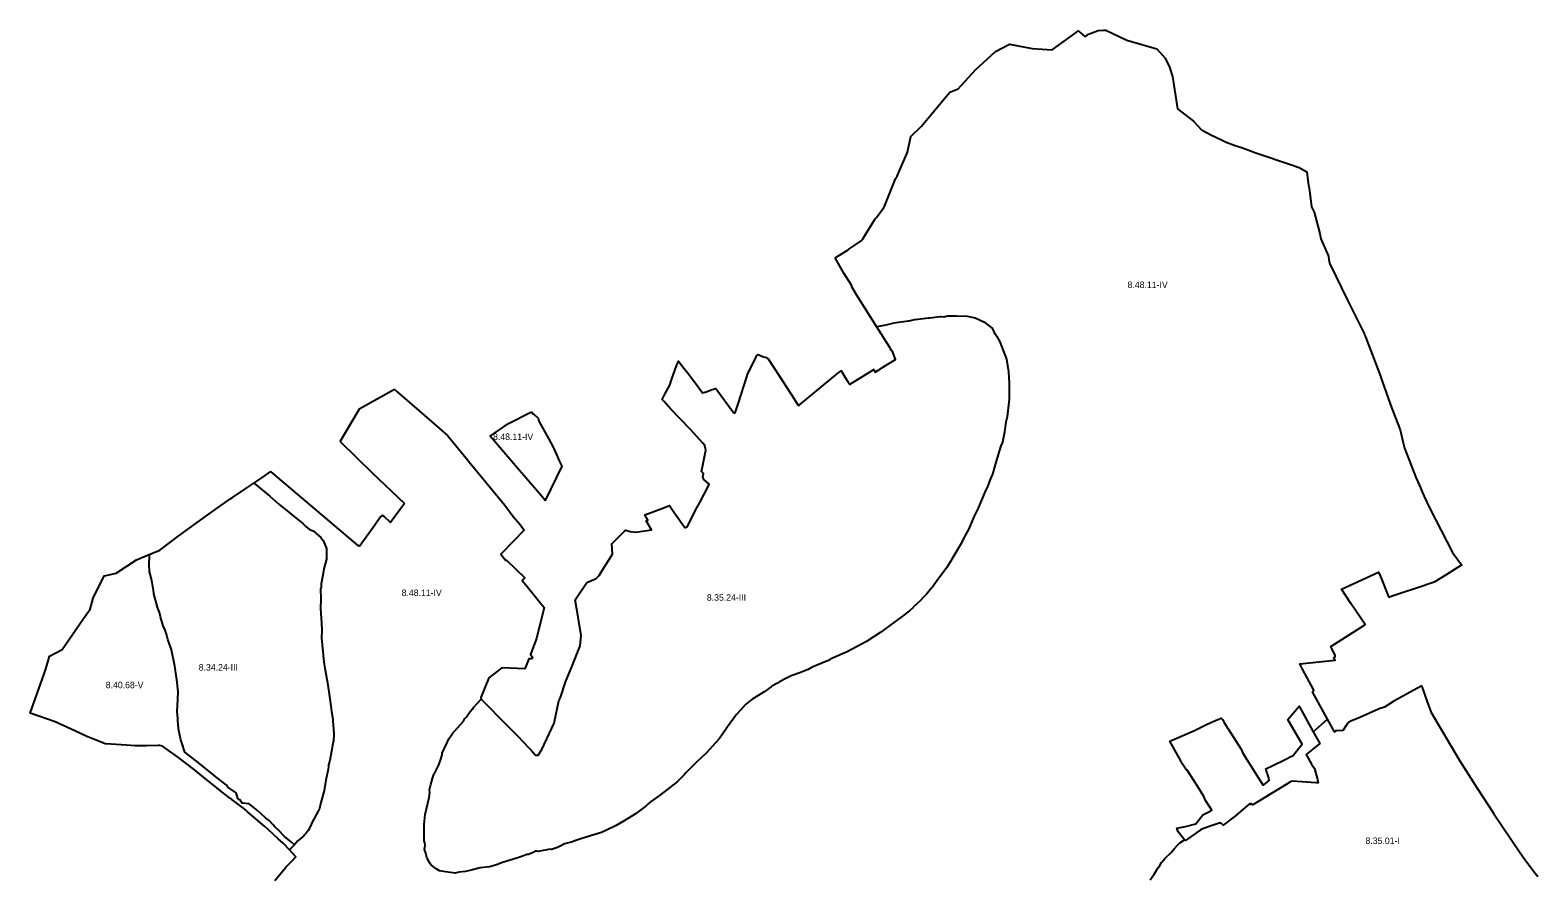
# Model space of a CAD drawing. Extents: x -444937 to -440470, y -1149084 to -1129741.
# Drawn here: x -443281 to -440963, y -1131040 to -1129741 of the extents above; entities that cross this region are included whole.
import ezdxf

# ---------------------------------------------------------------- set-up
doc = ezdxf.new("R2010")
doc.units = 0
doc.layers.add('Vrstva 28', color=7, linetype='Continuous')

msp = doc.modelspace()

# ---------------------------------------------------------------- linework, layer by layer
at = {"layer": 'Vrstva 28'}
for points in [[(-442043.23, -1130091.53), (-442040.49, -1130089.83), (-442039.92, -1130089.47), (-442039.17, -1130089.01), (-442023.03, -1130078.94), (-442021.83, -1130078.19), (-442012.81, -1130071.6), (-442003.19, -1130064.95), (-442000.52, -1130061.9), (-441981.34, -1130031.18), (-441979.75, -1130029.1), (-441968.28, -1130014.12), (-441967.99, -1130013.39), (-441951.57, -1129972.43), (-441949.67, -1129968.93), (-441947.95, -1129965.69), (-441931.73, -1129928.7), (-441926.71, -1129904.58), (-441910.67, -1129889.51), (-441869.52, -1129839.61), (-441866.98, -1129836.53), (-441853.91, -1129831.34), (-441827.5, -1129802.31), (-441796.73, -1129773.78), (-441775.18, -1129762.53), (-441740.41, -1129769.48), (-441709.58, -1129771.58), (-441668.73, -1129742.39), (-441666.17, -1129744.67), (-441659.09, -1129750.95), (-441655.75, -1129748.76), (-441653.67, -1129747.4), (-441638.81, -1129741.44), (-441630.48, -1129741.2), (-441627.01, -1129741.1)], [(-441627.01, -1129741.1), (-441594.36, -1129756.43), (-441548.54, -1129769.98), (-441535.75, -1129784.43), (-441528.76, -1129798.16), (-441524.48, -1129812.45), (-441516.67, -1129862.35), (-441492, -1129881.15), (-441479.58, -1129894.54), (-441478.61, -1129895.06), (-441464.46, -1129902.63), (-441458.68, -1129905.42), (-441448.22, -1129910.45), (-441441.62, -1129913.46), (-441428.07, -1129918.35), (-441415.24, -1129922.84), (-441397.66, -1129929.24), (-441396.28, -1129929.7), (-441343.12, -1129947.52), (-441329.41, -1129952.5), (-441318.04, -1129958.98), (-441316.2, -1129972.39), (-441315.02, -1129979.71), (-441314.71, -1129981.72), (-441313.77, -1129987.9), (-441310.82, -1130012.82), (-441306.53, -1130021.22), (-441297.94, -1130054.03), (-441296.52, -1130061.93), (-441284.64, -1130088.57), (-441284.44, -1130089.91), (-441283.82, -1130094.05), (-441283.09, -1130098.88), (-441282.96, -1130099.77), (-441282.57, -1130100.57), (-441255.11, -1130156.43), (-441229.36, -1130208.81), (-441228.53, -1130210.99), (-441227.78, -1130212.95), (-441204.67, -1130273.29), (-441204.43, -1130273.92), (-441189.48, -1130315.91), (-441186.17, -1130325.54), (-441174.46, -1130355.71), (-441170.23, -1130373.91), (-441167.88, -1130383.99), (-441160.47, -1130402.47), (-441149.43, -1130430.01), (-441144.79, -1130441.59), (-441137.17, -1130458.28), (-441128.64, -1130476.95), (-441094.04, -1130544.82), (-441079.55, -1130563.82), (-441079.42, -1130564), (-441082.38, -1130565.83), (-441090.64, -1130570.93), (-441103.48, -1130578.86), (-441122.26, -1130590.45), (-441129.52, -1130592.88), (-441139.81, -1130596.32), (-441181.79, -1130610.37), (-441185.15, -1130611.45), (-441189.02, -1130612.7), (-441191.79, -1130613.59)], [(-441979.49, -1130196.91), (-442010.04, -1130148.31), (-442017.48, -1130135.77), (-442018.12, -1130133.43), (-442029.81, -1130114.93), (-442043.23, -1130091.53)], [(-441839.96, -1130181.05), (-441828.05, -1130183.39), (-441814.24, -1130189.98), (-441801.69, -1130199.33), (-441798.72, -1130206.35), (-441794.04, -1130212.73), (-441791.77, -1130216.92), (-441789.79, -1130220.59), (-441779.8, -1130246.96), (-441776.61, -1130266.51), (-441775.33, -1130283.95), (-441775.76, -1130308.61), (-441778.52, -1130335.82), (-441780.65, -1130344.32), (-441781.54, -1130351.48), (-441782.56, -1130359.63), (-441785.75, -1130374.94), (-441786.02, -1130375.47), (-441787.87, -1130379.19), (-441791.06, -1130388.54), (-441797.59, -1130411.29), (-441801.27, -1130424.26), (-441802.2, -1130426.37), (-441805.31, -1130433.4), (-441808.71, -1130443.82), (-441811.7, -1130449.35), (-441812.96, -1130451.68), (-441819.53, -1130467.43), (-441822.1, -1130473.58), (-441822.51, -1130474.41), (-441822.72, -1130474.84), (-441822.89, -1130475.18), (-441829.54, -1130488.68), (-441837.83, -1130509.3), (-441844.64, -1130521.2), (-441849.1, -1130530.56), (-441863.63, -1130555.01), (-441865.65, -1130558.4), (-441871.17, -1130567.7), (-441871.21, -1130567.76), (-441886.11, -1130587.63), (-441894.17, -1130598.38), (-441895.51, -1130599.99), (-441902.25, -1130608.15), (-441907.57, -1130613.81), (-441911.95, -1130618.46), (-441912.45, -1130619), (-441923.12, -1130628.83), (-441923.85, -1130629.5), (-441928.82, -1130634.09), (-441941.58, -1130644.3), (-441968.75, -1130664.12), (-441969.87, -1130664.94), (-441971.34, -1130666.01), (-441973.05, -1130667.26), (-441995.16, -1130681.29), (-442024.72, -1130697.21), (-442028.32, -1130699.15), (-442043.44, -1130705.67), (-442047.03, -1130707.22), (-442051.19, -1130709.42), (-442053.38, -1130710.57), (-442054.68, -1130711.26), (-442078.49, -1130721.04), (-442084.44, -1130724.44), (-442098.9, -1130730.4), (-442110.81, -1130734.22), (-442114.65, -1130736.22), (-442117.79, -1130737.86), (-442128.69, -1130743.52), (-442131.9, -1130745.32), (-442140.57, -1130750.17), (-442141.69, -1130751.02), (-442150.61, -1130757.84), (-442152.26, -1130759.1), (-442163.02, -1130765.72), (-442169.47, -1130769.7), (-442173.31, -1130772.07), (-442180.96, -1130778.23), (-442188.89, -1130787.12), (-442194.99, -1130793.96), (-442196.33, -1130795.82), (-442208.55, -1130812.83), (-442209.42, -1130814.04), (-442211.7, -1130817.22), (-442221.57, -1130830.95), (-442241.34, -1130853.06), (-442256.22, -1130867.09), (-442256.28, -1130867.15), (-442273.04, -1130884.03), (-442274.98, -1130885.99), (-442286.2, -1130897.28), (-442313.2, -1130918.54), (-442327.23, -1130928.32), (-442331.26, -1130931.85), (-442333.83, -1130934.1), (-442335.73, -1130935.76), (-442350.19, -1130946.39), (-442367.66, -1130957.13)], [(-441979.49, -1130196.91), (-441978.44, -1130196.74), (-441964.54, -1130194.44), (-441954.19, -1130191.86), (-441949.23, -1130190.62), (-441930.66, -1130188.25), (-441929.25, -1130188.07), (-441921.04, -1130186.39), (-441919.9, -1130186.15), (-441899.77, -1130183.8), (-441897.29, -1130183.51), (-441881.64, -1130181.67), (-441879.93, -1130181.47), (-441876.1, -1130181.9), (-441870.15, -1130180.62), (-441856.54, -1130180.41), (-441839.96, -1130181.05)], [(-442020.82, -1130286.01), (-441987.93, -1130265.66), (-441983.86, -1130263.14), (-441983.7, -1130263.41), (-441981.52, -1130267.12), (-441973.17, -1130261.95), (-441971.23, -1130260.75), (-441950.1, -1130247.67), (-441954.62, -1130236.67), (-441956.47, -1130233.71), (-441959.25, -1130229.27), (-441979.49, -1130196.91)], [(-442433.7, -1130672.39), (-442438.82, -1130641.1), (-442442.7, -1130617.43), (-442425.08, -1130590.72), (-442410.35, -1130584.67), (-442405.99, -1130579.98), (-442401.18, -1130572.38), (-442385.25, -1130547.17), (-442386.53, -1130531.38), (-442372.85, -1130517.54), (-442366.77, -1130511), (-442365.07, -1130510.15), (-442358.27, -1130512.27), (-442349.76, -1130513.55), (-442325.44, -1130509.6), (-442333.77, -1130495.69), (-442331.01, -1130494.8), (-442332.54, -1130492.29), (-442334.31, -1130489.4), (-442336.01, -1130486.62), (-442325.81, -1130482.86), (-442309.69, -1130476.92), (-442300.54, -1130473.55), (-442297.58, -1130472.46), (-442295.76, -1130475.28), (-442292.89, -1130479.91), (-442290.88, -1130483.15), (-442286.68, -1130488.9), (-442284.05, -1130492.52), (-442280.75, -1130497.03), (-442274.29, -1130505.9), (-442272.8, -1130506.32), (-442272.06, -1130505.82), (-442270.89, -1130505.05), (-442255.78, -1130476.07), (-442251.43, -1130467.72), (-442239.12, -1130444.1), (-442236.7, -1130439.47), (-442245.12, -1130432.2), (-442246.63, -1130428.44), (-442245.69, -1130422.94), (-442248.57, -1130420.01), (-442247.13, -1130412.78), (-442242.08, -1130387.35), (-442243.5, -1130380.36), (-442243.59, -1130379.9), (-442247.33, -1130375.82), (-442264.97, -1130356.15), (-442266.43, -1130354.53), (-442295.76, -1130323.91), (-442299.37, -1130319.91), (-442306.2, -1130312.32), (-442309.16, -1130309.03), (-442308.79, -1130308.36), (-442304.93, -1130301.19), (-442297.46, -1130287.35), (-442294.57, -1130278.93), (-442286.62, -1130255.88), (-442284.61, -1130251.59), (-442284.04, -1130250.36), (-442283.73, -1130250.75), (-442277.61, -1130258.54), (-442270.68, -1130267.36), (-442259.58, -1130282.17), (-442247.08, -1130298.83), (-442241.34, -1130297.55), (-442231.99, -1130293.94), (-442228.39, -1130292.65), (-442226.78, -1130292.07), (-442199.46, -1130329.02), (-442197.55, -1130330.08), (-442197.27, -1130329.94), (-442196.69, -1130329.65), (-442194.14, -1130322.21), (-442191.6, -1130314.25), (-442178.82, -1130274.26), (-442177.77, -1130270.98), (-442164.81, -1130243.63), (-442164.17, -1130242.28), (-442162.25, -1130239.94), (-442160.68, -1130240.58), (-442153.33, -1130243.55), (-442149.29, -1130244.4), (-442147.1, -1130245.92), (-442146.52, -1130246.32), (-442146.19, -1130246.82), (-442128.87, -1130273.22), (-442105.89, -1130308.24), (-442100.39, -1130317.32), (-442099.33, -1130318.39), (-442098.48, -1130318.17), (-442039.37, -1130269.07), (-442034.07, -1130265.25), (-442033.59, -1130266.01), (-442033.18, -1130265.67), (-442027.66, -1130275.3), (-442022.86, -1130282.82), (-442021.73, -1130284.58), (-442020.82, -1130286.01)], [(-442804.09, -1130373.76), (-442776.45, -1130327.08), (-442774.04, -1130323.01), (-442720.69, -1130293.35)], [(-442720.69, -1130293.35), (-442716.51, -1130297.67), (-442682.91, -1130326.42), (-442651.72, -1130353.78), (-442638.9, -1130365.03), (-442607.72, -1130402.76), (-442606.77, -1130403.91), (-442550.89, -1130471.96), (-442538.14, -1130488.97), (-442527.51, -1130501.72), (-442525.44, -1130504.67), (-442521.55, -1130510.23), (-442556.21, -1130546.37), (-442557.22, -1130547.38), (-442551.46, -1130554.43), (-442549.35, -1130557), (-442548.67, -1130556.55), (-442520.3, -1130583.3), (-442524.35, -1130587.57), (-442518.74, -1130594.43), (-442495.48, -1130622.9), (-442490.57, -1130628.93), (-442502.12, -1130676.66), (-442503.17, -1130679.42), (-442511.68, -1130701.43), (-442507.95, -1130706.02), (-442509.44, -1130708.14), (-442514.35, -1130708.33), (-442520.25, -1130723.59), (-442555.52, -1130721.77), (-442575.4, -1130737.4), (-442587.88, -1130767.45), (-442587.51, -1130770.05)], [(-442500, -1130338.12), (-442498.79, -1130342.62), (-442483.88, -1130369.46), (-442476.9, -1130382.59), (-442470.16, -1130397.39), (-442467.28, -1130403.83), (-442463.43, -1130411.9), (-442488.8, -1130464.73), (-442495.89, -1130456.48), (-442518.83, -1130429.78), (-442531.49, -1130414.9), (-442573.49, -1130365.51), (-442545.58, -1130346.1), (-442510.06, -1130328.22)], [(-442510.06, -1130328.22), (-442507.97, -1130331.59), (-442507.17, -1130331.16), (-442500, -1130338.12)], [(-442804.09, -1130373.76), (-442754.81, -1130421.97), (-442705.43, -1130469.26)], [(-442936.98, -1130437.83), (-442924.6, -1130429.5), (-442910.63, -1130420.09)], [(-442705.43, -1130469.26), (-442726.82, -1130498.57), (-442736.69, -1130489.18), (-442739.03, -1130487.91), (-442740.3, -1130488.12), (-442742, -1130489.82), (-442750.96, -1130502.49), (-442773.25, -1130534.04), (-442774.95, -1130534.67), (-442776.02, -1130534.25), (-442906.77, -1130423.37), (-442910.63, -1130420.09)], [(-443097.02, -1130547.24), (-443095.23, -1130546.49), (-443081.71, -1130540.83), (-443053.63, -1130519.95), (-443027.65, -1130501.18), (-442998.28, -1130479.96), (-442974.07, -1130462.8), (-442969.91, -1130460), (-442948.01, -1130445.26), (-442936.98, -1130437.83)], [(-442936.98, -1130437.83), (-442936.7, -1130438.06), (-442935.36, -1130439.15), (-442912.28, -1130457.93), (-442898.68, -1130470.05), (-442861.9, -1130499.81), (-442856.8, -1130504.7), (-442851.48, -1130508.95), (-442845.72, -1130511.39)], [(-442845.72, -1130511.39), (-442833.97, -1130521.68), (-442830.38, -1130526.26), (-442825.42, -1130538.49), (-442825.14, -1130555.02), (-442829.38, -1130569.75), (-442830.34, -1130576.35), (-442830.38, -1130576.65), (-442831.42, -1130581.78), (-442833.63, -1130592.71), (-442833.63, -1130598.66), (-442834.26, -1130600.36), (-442833.84, -1130616.09), (-442834.48, -1130630.55), (-442833.49, -1130646.29), (-442833.08, -1130652.93), (-442832.35, -1130664.56), (-442832.78, -1130675.62), (-442829.38, -1130713.03), (-442827.66, -1130722.55), (-442823.64, -1130744.92), (-442820.68, -1130765.84), (-442818.54, -1130780.96), (-442817.39, -1130789.1), (-442815.71, -1130801.02), (-442815.34, -1130803.59), (-442814.31, -1130816.56), (-442814.28, -1130817.01), (-442813.86, -1130822.3), (-442814.05, -1130825.13), (-442814.71, -1130834.63), (-442814.94, -1130835.95), (-442820.02, -1130864.39), (-442821.94, -1130871.19), (-442822.32, -1130874.03), (-442823.21, -1130880.55), (-442826.4, -1130895), (-442827.17, -1130900.76), (-442828.1, -1130907.76), (-442828.89, -1130910.76), (-442834.34, -1130931.41), (-442836.18, -1130938.37), (-442838.31, -1130942.53), (-442847.59, -1130960.64), (-442850.07, -1130965.48), (-442853.5, -1130972.17), (-442853.61, -1130972.38), (-442856.76, -1130976.26), (-442859.03, -1130979.06), (-442859.99, -1130980.25), (-442863.39, -1130983.17), (-442869.13, -1130988.11), (-442872.84, -1130992.45), (-442874.33, -1130994.19)], [(-442882.23, -1131001.82), (-442891.39, -1130992.04), (-442895.35, -1130988.44), (-442899.33, -1130984.82), (-442906.63, -1130978.19), (-442915.59, -1130970.05), (-442919.98, -1130966.06), (-442940.07, -1130948.87), (-442946.49, -1130943.37), (-442949.68, -1130940.64), (-442952.16, -1130938.52), (-442960.65, -1130932.13), (-442970.89, -1130924.41), (-442971.95, -1130923.61), (-442972.2, -1130923.41), (-442974.22, -1130921.83), (-442988, -1130911.01), (-443002.15, -1130899.89), (-443003.41, -1130898.87), (-443009.46, -1130894.01), (-443030.66, -1130876.94), (-443054.28, -1130859.03), (-443054.57, -1130858.81), (-443070.13, -1130847.71), (-443077.41, -1130842.52), (-443081.59, -1130841.29), (-443084.12, -1130841.36), (-443102.37, -1130841.84), (-443109.42, -1130842.03), (-443110.44, -1130841.97), (-443118.52, -1130841.76), (-443119.22, -1130841.72), (-443133.41, -1130840.86), (-443156.14, -1130839.47), (-443165.45, -1130838.96), (-443176.89, -1130834.39), (-443192.31, -1130828.23), (-443192.7, -1130828.08), (-443204.51, -1130822.59), (-443230.29, -1130810.62), (-443242.27, -1130805.06), (-443280.95, -1130791.54), (-443259.33, -1130731.05), (-443257.22, -1130725.15), (-443253.77, -1130713.08), (-443251.22, -1130704.16), (-443231.83, -1130693.59), (-443199.74, -1130647.63), (-443198.69, -1130646.13), (-443188.44, -1130631.49), (-443184.16, -1130614.88), (-443167.28, -1130580.57), (-443161.99, -1130579.3), (-443148.93, -1130576.18), (-443117.23, -1130555.7), (-443097.02, -1130547.24)], [(-443047.81, -1130837.23), (-443049.4, -1130832.5), (-443052.25, -1130818.42), (-443053.01, -1130814.65), (-443053.75, -1130803.52), (-443054, -1130799.84), (-443054.71, -1130789.14), (-443053.98, -1130770.97), (-443053.44, -1130757.67), (-443054.16, -1130749.97), (-443054.71, -1130744.07), (-443055.8, -1130737.05), (-443058.54, -1130719.41), (-443063.84, -1130694.44), (-443064.49, -1130691.35), (-443069.38, -1130678.59), (-443071.3, -1130670.09), (-443073.53, -1130664.27), (-443076.19, -1130657.34), (-443080.44, -1130643.73), (-443081.29, -1130638.63), (-443085.33, -1130628.42), (-443090.62, -1130608.05), (-443090.85, -1130607.16), (-443091.46, -1130603.19), (-443093.83, -1130587.61), (-443097.44, -1130574), (-443098.08, -1130563.59), (-443097.19, -1130549.85), (-443097.02, -1130547.24)], [(-441286.04, -1130800.83), (-441309.13, -1130758.68), (-441306.98, -1130756.33), (-441324.42, -1130724.02), (-441328.78, -1130715.93), (-441274.46, -1130710.17), (-441276.3, -1130706.33), (-441275.09, -1130706.16), (-441274.03, -1130704.89), (-441274.46, -1130703.18), (-441279.56, -1130692.13), (-441281.04, -1130688.93), (-441229.94, -1130657.08), (-441230.31, -1130656.54), (-441228.22, -1130655.29), (-441250, -1130622.89), (-441264.26, -1130600.91), (-441207.65, -1130574.64), (-441204.57, -1130581.55), (-441191.79, -1130613.59)], [(-442587.51, -1130770.05), (-442586.61, -1130770.97), (-442547.44, -1130810.59), (-442529.69, -1130828.54), (-442523.11, -1130835.19), (-442522.62, -1130835.69), (-442514.1, -1130844.99), (-442510.71, -1130848.68), (-442503.91, -1130856.1), (-442502.42, -1130856.1), (-442500, -1130856.11), (-442494.33, -1130847.75), (-442475.2, -1130806.93), (-442474.67, -1130804.47), (-442467.97, -1130772.92), (-442467.94, -1130772.85), (-442465.63, -1130767.81), (-442457.12, -1130742.3), (-442447.89, -1130720.58), (-442435.09, -1130688.21), (-442433.7, -1130672.39)], [(-441141.16, -1130749.48), (-441148.72, -1130753.75), (-441183.89, -1130773.34), (-441198.35, -1130782.27), (-441206.43, -1130785.03), (-441236.33, -1130798.17), (-441250, -1130804.18), (-441253.83, -1130805.87), (-441255.54, -1130807.36), (-441257.52, -1130811.07), (-441257.64, -1130811.12), (-441261.55, -1130817.42), (-441262.98, -1130818.2), (-441272.54, -1130819.05), (-441275.28, -1130820.48), (-441286.04, -1130800.83)], [(-441141.16, -1130749.48), (-441140.75, -1130750.7), (-441133.27, -1130772.61), (-441127.89, -1130788.34), (-441127.2, -1130789.51)], [(-442367.66, -1130957.13), (-442379.95, -1130964.68), (-442395.52, -1130972.14), (-442400.36, -1130974.46), (-442402.33, -1130975.06), (-442405.95, -1130976.17), (-442434.38, -1130984.87), (-442443.21, -1130988.26), (-442447.13, -1130989.76), (-442459.04, -1130992.74), (-442464.09, -1130995.26), (-442470.09, -1130998.27), (-442477.75, -1131001.03), (-442479.45, -1131001.45), (-442481.15, -1131001.03), (-442500, -1131004.42), (-442502.54, -1131003.88), (-442503.7, -1131003.63), (-442506.25, -1131005.33), (-442507.66, -1131005.93), (-442514.75, -1131008.95), (-442515.98, -1131009.05), (-442517.3, -1131009.16), (-442522.4, -1131011.07), (-442530.91, -1131014.26), (-442554.72, -1131021.28), (-442564.09, -1131024.87), (-442567.47, -1131026.17), (-442574.27, -1131027.87), (-442588.73, -1131029.78), (-442600.95, -1131032.72), (-442611.69, -1131035.31), (-442621.04, -1131036.16), (-442623.33, -1131036.73), (-442627, -1131037.65), (-442642.05, -1131035.68), (-442651.44, -1131034.46), (-442655.39, -1131031.8), (-442660.58, -1131028.29), (-442664.62, -1131024.25), (-442666.75, -1131021.7), (-442670.71, -1131014.2), (-442670.79, -1131014.05), (-442672.77, -1131007.05), (-442674.4, -1131001.29), (-442674.37, -1131000.98), (-442673.76, -1130995.34), (-442674.19, -1130991.09), (-442675.04, -1130989.39), (-442675.1, -1130982.35), (-442675.16, -1130974.12), (-442675.23, -1130965.98), (-442675.25, -1130962.82), (-442673.77, -1130947.74), (-442673.76, -1130947.72), (-442667.6, -1130921.36), (-442666.54, -1130913.71), (-442666.54, -1130913.68), (-442666.96, -1130909.46), (-442664.9, -1130901.6), (-442662.5, -1130892.45), (-442660.06, -1130885.96), (-442659.95, -1130885.65), (-442652.51, -1130871.19), (-442650.19, -1130863.93), (-442647.62, -1130855.89), (-442647.62, -1130853.12), (-442644.92, -1130847.5), (-442641.9, -1130841.23), (-442636.99, -1130831.02), (-442633.36, -1130825.87), (-442630.4, -1130821.66), (-442627.94, -1130818.91), (-442614.45, -1130803.81), (-442612.54, -1130799.77), (-442609.99, -1130797.43), (-442604.13, -1130789.34), (-442600.86, -1130784.83), (-442600.44, -1130785.36), (-442599.47, -1130782.92), (-442599.36, -1130782.76), (-442587.51, -1130770.05)], [(-441506.13, -1130986.55), (-441515.54, -1130974.03), (-441517.88, -1130968.72), (-441504.49, -1130966.16), (-441488.71, -1130962.01), (-441488.33, -1130961.91), (-441477.7, -1130948.09), (-441466.43, -1130942.35), (-441464.81, -1130941.53), (-441464.06, -1130941.15), (-441473.87, -1130925.98), (-441476.42, -1130920.03), (-441485.78, -1130903.87), (-441492.57, -1130893.67), (-441500.66, -1130881.13), (-441502.02, -1130879.01), (-441502.87, -1130879.52), (-441512.32, -1130865.52), (-441511.33, -1130864.84), (-441528.48, -1130834.78), (-441490.45, -1130818.2), (-441470.9, -1130808.63), (-441458.47, -1130803.17), (-441451.92, -1130800.28), (-441449.64, -1130799.28), (-441447.51, -1130801.4), (-441444.96, -1130806.29), (-441441.89, -1130811.09), (-441439.2, -1130815.79), (-441438.94, -1130815.71), (-441419.02, -1130846.9), (-441416.05, -1130853.28), (-441385.43, -1130901.75), (-441384.96, -1130901.81), (-441383.73, -1130901.96), (-441375.65, -1130895.37), (-441376.93, -1130889.42), (-441380.33, -1130879.21), (-441381.01, -1130877.16), (-441370.33, -1130871.96), (-441351.36, -1130862.74), (-441341.15, -1130857.88), (-441339.51, -1130857.1), (-441330.16, -1130845.62), (-441327.14, -1130841.92), (-441325.12, -1130839.44), (-441345.04, -1130804.8), (-441346.83, -1130801.5), (-441329.53, -1130781.05), (-441307.82, -1130820.19)], [(-441307.82, -1130820.19), (-441286.04, -1130800.83)], [(-441127.2, -1130789.51), (-441083.55, -1130863.55), (-441069.43, -1130886.07), (-441056, -1130907.27), (-441045.35, -1130923.53), (-441032.99, -1130942.46), (-441030.18, -1130946.6), (-440989.66, -1131006.42), (-440983.75, -1131015.14), (-440968.54, -1131035.29), (-440962.58, -1131043.2)], [(-441307.82, -1130820.19), (-441297.76, -1130838.31), (-441308.66, -1130847.09), (-441318.89, -1130855.43), (-441310.54, -1130870.38), (-441306.08, -1130876.9), (-441301.46, -1130893.67), (-441300.23, -1130898.86), (-441304.01, -1130898.63), (-441339.94, -1130896.43), (-441342.06, -1130896.86), (-441343.71, -1130897.89), (-441349.35, -1130901.44), (-441401.01, -1130932.6), (-441403.29, -1130931.3), (-441404.4, -1130932.2), (-441405.46, -1130930.72), (-441427.49, -1130949.79), (-441446.55, -1130964.12), (-441448.78, -1130961.28), (-441450.49, -1130960.42), (-441451.77, -1130960.85), (-441452.14, -1130960.32), (-441453.97, -1130961.2), (-441466.66, -1130965.66), (-441479.48, -1130970.17), (-441481.8, -1130971.66), (-441504.3, -1130987.7), (-441506.13, -1130986.55)], [(-442874.33, -1130994.19), (-442879.16, -1130990.16), (-442881.58, -1130988.14), (-442889.75, -1130981.31), (-442899.05, -1130971.44), (-442904.42, -1130966.86), (-442907.51, -1130963.41), (-442913.56, -1130956.65), (-442919.3, -1130952.83), (-442931.42, -1130941.35), (-442941.53, -1130933.39), (-442944.38, -1130931.14), (-442954.8, -1130930.29), (-442956.02, -1130928.38), (-442958.2, -1130924.98), (-442960.54, -1130924.34), (-442961.6, -1130922.85), (-442964.3, -1130914.3), (-442965.49, -1130913.47), (-442976.91, -1130905.42), (-442979.03, -1130902.44), (-442979.48, -1130902.09), (-442995.36, -1130889.44), (-443001.59, -1130884.47), (-443012.02, -1130876.17), (-443022.73, -1130867.63), (-443043.03, -1130851.46), (-443047.81, -1130837.23)], [(-441558.67, -1131048.1), (-441552.77, -1131039.3), (-441548.92, -1131033.56), (-441547.85, -1131031.01), (-441546.03, -1131028.7), (-441544.02, -1131026.16), (-441541.48, -1131021.65), (-441540.42, -1131020.38), (-441536.16, -1131015.27), (-441526.38, -1131005.92), (-441521.64, -1131000.39), (-441516.18, -1130994.01), (-441515.18, -1130993.08)], [(-441515.18, -1130993.08), (-441512.99, -1130991.04), (-441507.37, -1130987.37), (-441506.13, -1130986.55)], [(-442904.54, -1131049.3), (-442887.1, -1131028.05), (-442882.25, -1131023), (-442879.56, -1131020.2), (-442878.7, -1131019.3), (-442872.21, -1131012.5), (-442882.23, -1131001.82)], [(-442874.33, -1130994.19), (-442879.01, -1130998.71), (-442880.7, -1131000.34), (-442882.23, -1131001.82)]]:
    msp.add_lwpolyline(points, dxfattribs=at)

# ---------------------------------------------------------------- texts
for s, p in [('8.48.11-IV', (-441593.46, -1130137.78)), ('8.48.11-IV', (-442569.07, -1130371.58)), ('8.48.11-IV', (-442709.72, -1130611.56)), ('8.35.24-III', (-442240.37, -1130618.72)), ('8.34.24-III', (-443021.71, -1130726.25)), ('8.40.68-V', (-443164.7, -1130753.38)), ('8.35.01-I', (-441227.63, -1130992.98))]:
    msp.add_text(s, height=10, dxfattribs=at).set_placement(p)

doc.saveas('drawing.dxf')
